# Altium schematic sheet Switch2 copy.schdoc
size 299 x 308 mm
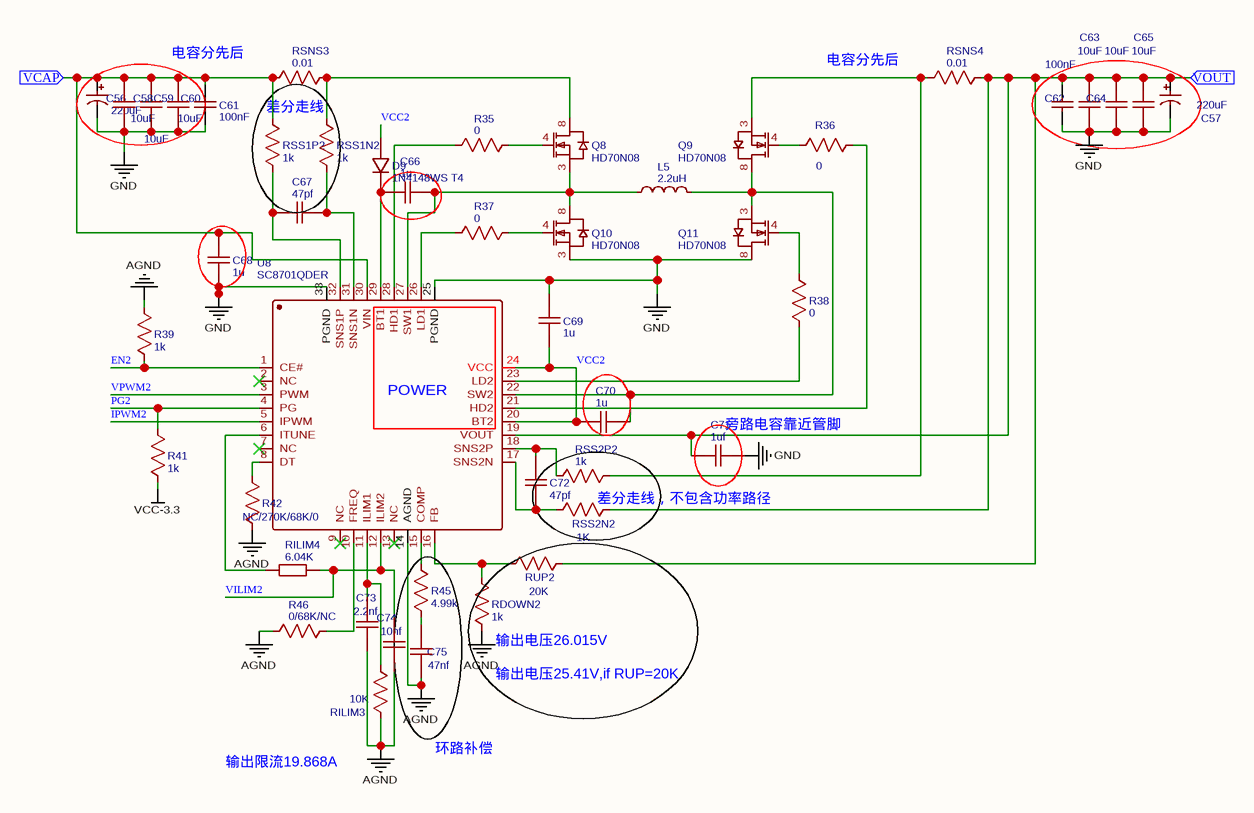
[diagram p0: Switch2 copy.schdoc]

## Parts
C56  220uF  [CAP-SMD_BD10.0-L10.3-W10.3-FD]
C57  220uF  [CAP-SMD_BD10.0-L10.3-W10.3-FD]
C58  10uF  [C1206]
C59  10uF  [C1206]
C60  10uF  [C1206]
C61  100nF  [C0603]
C62  100nF  [C0603]
C63  10uF  [C1206]
C64  10uF  [C1206]
C65  10uF  [C1206]
C66  1u  [C0402]
C67  47pf  [C0402]
C68  1u  [C0402]
C69  1u  [C0402]
C70  1u  [C0402]
C71  1uf  [C0402]
C72  47pf  [C0402]
C73  2.2nf  [C0402]
C74  10nf  [C0402]
C75  47nf  [C0402]
D9  1N4148WS T4  [SOD-323_L1.8-W1.3-LS2.5-FD]
L5  2.2uH  [IND-SMD_L17.5-W17.0_YXMAC1770]
Q8  HD70N08  [PDFN-8_L4.9-W5.8-P1.27-LS6.1-BL FOR3]
Q9  HD70N08  [PDFN-8_L4.9-W5.8-P1.27-LS6.1-BL FOR3]
Q10  HD70N08  [PDFN-8_L4.9-W5.8-P1.27-LS6.1-BL FOR3]
Q11  HD70N08  [PDFN-8_L4.9-W5.8-P1.27-LS6.1-BL FOR3]
R35  0  [R0603]
R36  0  [R0603]
R37  0  [R0603]
R38  0  [R0603]
R39  1k  [R0402]
R41  1k  [R0402]
R42  NC/270K/68K/0  [R0402]
R45  4.99k  [R0402]
R46  0/68K/NC  [R0402]
RDOWN2  1k  [R0402]
RILIM3  10K  [R0402]
RILIM4  6.04K  [R0402]
RSNS3  0.01  [R0805]
RSNS4  0.01  [R0805]
RSS1N2  1k  [R0402]
RSS1P2  1k  [R0402]
RSS2N2  1K  [R0402]
RSS2P2  1k  [R0402]
RUP2  20K  [R0402]
U8  SC8701QDER  [QFN-32_L4.0-W4.0-P0.4-BL-EP2.6]

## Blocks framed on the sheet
POWER: U8

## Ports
VCAP (in), VOUT (in)

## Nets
AGND: C73.1 C74.1 C75.1 R39.2 R42.1 R46.1 RDOWN2.1 RILIM3.1 U8.14(AGND)
GND: C56.2 C57.2 C58.1 C59.1 C60.1 C61.1 C62.1 C63.1 C64.1 C65.1 C68.1 C69.2 C71.1 Q10.3(S) Q11.8(D) U8.25(PGND) U8.33(PGND)
VCC-3.3: R41.1
EN2: R39.1 U8.1(CE#)
IPWM2: U8.5(IPWM)
PG2: R41.2 U8.4(PG)
VCAP: C56.1 C58.2 C59.2 C60.2 C61.2 C68.2 RSNS3.1 RSS1P2.2 U8.30(VIN) ; port VCAP
VCC2: C69.1 C70.2 D9.1(A) U8.20(BT2) U8.24(VCC)
VILIM2: C74.2 RILIM4.2 U8.12(ILIM2)
VOUT: C57.1 C62.2 C63.2 C64.2 C65.2 C71.2 RSNS4.2 RSS2N2.2 RUP2.2 U8.19(VOUT) ; port VOUT
VPWM2: U8.3(PWM)
NetC66_1: C66.1 D9.2(K) U8.29(BT1)
NetC66_2: C66.2 L5.1 Q8.3(S) Q10.8(D) U8.27(SW1)
NetC67_1: C67.1 RSS1N2.1 U8.31(SNS1N)
NetC67_2: C67.2 RSS1P2.1 U8.32(SNS1P)
NetC70_1: C70.1 L5.2 Q9.8(D) Q11.3(S) U8.22(SW2)
NetC72_1: C72.1 RSS2P2.1 U8.18(SNS2P)
NetC72_2: C72.2 RSS2N2.1 U8.17(SNS2N)
NetC73_2: C73.2 RILIM3.2 U8.11(ILIM1)
NetC75_2: C75.2 R45.1
NetQ8_4: Q8.4(G) R35.2
NetQ8_8: Q8.8(D) RSNS3.2 RSS1N2.2
NetQ9_3: Q9.3(S) RSNS4.1 RSS2P2.2
NetQ9_4: Q9.4(G) R36.1
NetQ10_4: Q10.4(G) R37.2
NetQ11_4: Q11.4(G) R38.2
NetR35_1: R35.1 U8.28(HD1)
NetR36_2: R36.2 U8.21(HD2)
NetR37_1: R37.1 U8.26(LD1)
NetR38_1: R38.1 U8.23(LD2)
NetR42_2: R42.2 U8.8(DT)
NetR45_2: R45.2 U8.15(COMP)
NetR46_2: R46.2 U8.10(FREQ)
NetRDOWN2_2: RDOWN2.2 RUP2.1 U8.16(FB)
NetRILIM4_1: RILIM4.1 U8.6(ITUNE)

Not connected (* = marked no-connect by the designer): U8 2(NC)* 7(NC)* 9(NC)* 13(NC)*

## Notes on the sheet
- 电容分先后
- (near RSS1P2) 差分走线
- (near C63) C64
- (near C71) 旁路电容靠近管脚
- (near RSS2N2) 差分走线，不包含功率路径
- (near RDOWN2) 输出电压26.015V
- (near RDOWN2) 输出电压25.41V,if RUP=20K
- 输出限流19.868A
- 环路补偿

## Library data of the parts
C56 C57 = 220uF: BOM_Manufacturer: CapXon; BOM_Manufacturer Part: DV221M050G105A; nameAlias: Capacitance
C58-C60 C63-C65 = 10uF: BOM_Manufacturer: MuRata; BOM_Manufacturer Part: GRM31CR61H106KA12L; nameAlias: Capacitance
C61 C62 = 100nF: BOM_Manufacturer Part: CL10B104JB8NNNC; BOM_Manufacturer: SAMSUNG; nameAlias: Capacitance; SMT Type: Extend
C66 C68-C70 = 1u: nameAlias: Value(F)
C67 C72 = 47pf: nameAlias: Value(F)
C71 = 1uf: nameAlias: Value(F)
C73 = 2.2nf: nameAlias: Value(F)
C74 = 10nf: nameAlias: Value(F)
C75 = 47nf: nameAlias: Value(F)
D9 = 1N4148WS T4: BOM_Manufacturer: CJ; SMT Type: Basic
L5 = 2.2uH: BOM_Manufacturer: YUXIN TECH; BOM_Manufacturer Part: YXMAC1770-2R2M-IGP; nameAlias: Inductance; Contributor: LCSC
Q8-Q11 = HD70N08: BOM_Manufacturer: HL; Contributor: LCSC
R35-R38 = 0: nameAlias: Value(Ω)
R39 R41 RDOWN2 RSS1N2 RSS1P2 RSS2P2 = 1k: nameAlias: Value(Ω)
R42 = NC/270K/68K/0: nameAlias: Value(Ω)
R45 = 4.99k: nameAlias: Value(Ω)
R46 = 0/68K/NC: nameAlias: Value(Ω)
RILIM3 = 10K: nameAlias: Value(Ω)
RILIM4 = 6.04K: BOM_Manufacturer: WTC; BOM_Manufacturer Part: WR04X6041FTL; nameAlias: Resistance (Ohms); Contributor: LCSC
RSNS3 RSNS4 = 0.01: nameAlias: Value(Ω)
RSS2N2 = 1K: nameAlias: Value(Ω)
RUP2 = 20K: nameAlias: Value(Ω)
U8 = SC8701QDER: BOM_Manufacturer: Southchip Semicon; Contributor: LCSC; SMT Type: Extend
